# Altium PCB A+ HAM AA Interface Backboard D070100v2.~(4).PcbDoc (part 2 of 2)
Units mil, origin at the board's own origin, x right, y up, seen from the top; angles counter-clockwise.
Board outline 2600 x 10000 mil, 6 copper layers (Top Layer, InternalPlane1, MidLayer1, InternalPlane3, InternalPlane4, Bottom Layer), stack 92.2 mil thick; 10 components, 66 nets, 166 pads, 1741 vias.
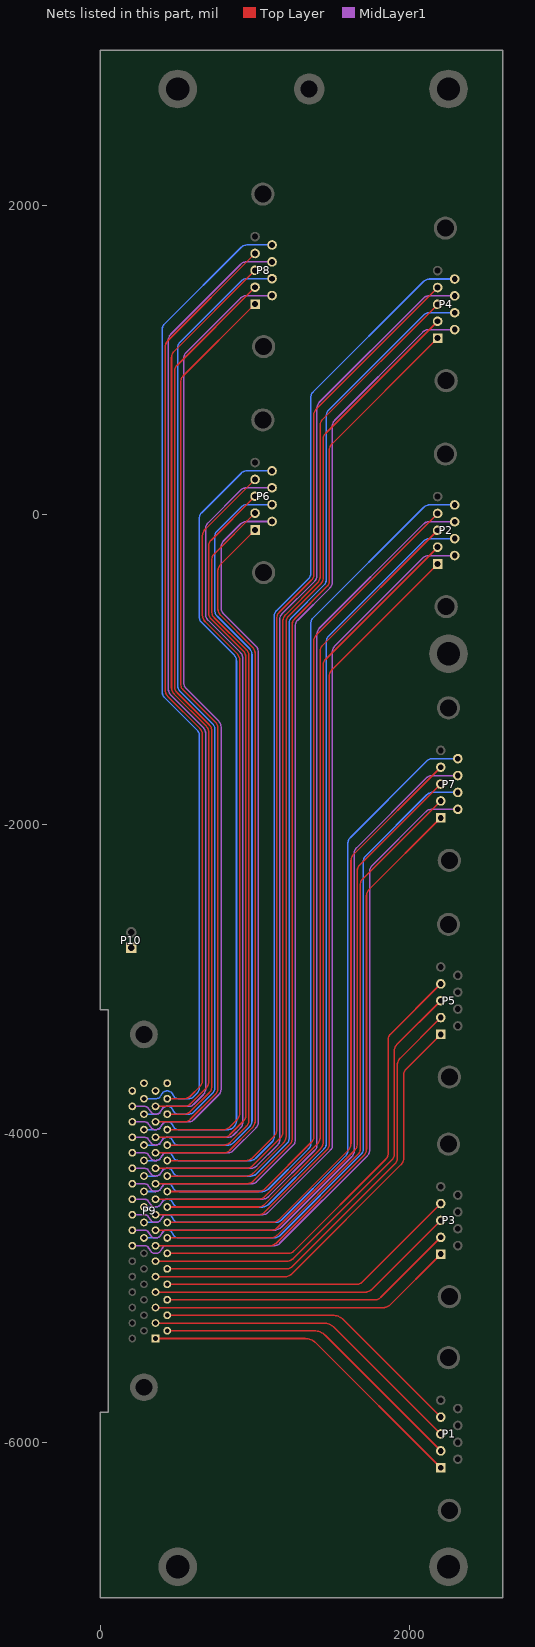
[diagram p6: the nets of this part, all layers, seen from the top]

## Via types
v1: diameter 12, hole 10, Top Layer to Bottom Layer, 1741 vias

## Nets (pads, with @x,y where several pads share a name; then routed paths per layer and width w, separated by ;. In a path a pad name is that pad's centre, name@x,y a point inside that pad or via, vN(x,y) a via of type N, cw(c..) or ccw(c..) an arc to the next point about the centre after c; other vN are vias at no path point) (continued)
OUTPUTN13: P7.6 P9.47 | length 4398.4
  MidLayer1 w10: P9.47@206.81,-4725 280,-4725 ; 281.81,-4725 cw(c281.81,-4775) 307.3,-4731.99 ; 406.18,-4732.07 382.54,-4767.87 cw(c356.81,-4725) 356.81,-4775 cw(c356.81,-4725) 331.08,-4767.87 307.44,-4732.07 ; 406.32,-4731.99 cw(c431.81,-4775) 431.81,-4725 1123.79,-4725 ccw(c1123.79,-4673.79) 1159.98,-4710.02 1725.03,-4144.97 ccw(c1688.79,-4108.79) 1740,-4108.81 ; 1740,-4105 1740,-4108.79 ; 1740,-2315 1740,-2306.21 ; 1740,-2306.15 cw(c1791.21,-2306.21) 1740,-2306.07 ; 2141.19,-1905 ccw(c2141.21,-1956.21) 2141.07,-1905 ; P7.6@2310,-1905 2141.07,-1905 ; 307.3,-4731.99 cw(c356.81,-4725) 307.28,-4731.82 307.44,-4732.07 ; 307.3,-4731.99 cw(c281.81,-4775) 307.44,-4732.07 ; 1740,-4108.81 1740,-2306.07 ; 1740,-2306.07 cw(c1791.21,-2306.21) 1754.94,-2270.06 cw(c1791.21,-2306.21) 1755,-2270 2105.06,-1919.94 cw(c2141.21,-1956.21) 2141.07,-1905
OUTPUTN14: P7.7 P9.48 | length 4366.6
  Bottom Layer w10: P9.48@281.81,-4675 355,-4675 ; 356.81,-4675 ccw(c356.81,-4625) 382.3,-4668.01 ; 481.18,-4667.93 457.54,-4632.13 ccw(c431.81,-4675) 431.81,-4625 ccw(c431.81,-4675) 406.08,-4632.13 382.44,-4667.93 ; 481.32,-4668.01 ccw(c506.81,-4625) 506.81,-4675 1124,-4675 ccw(c1124,-4624.3) 1159.83,-4660.17 1685.17,-4134.83 ccw(c1649.3,-4099) 1700,-4099 1700,-2242 cw(c1750.7,-2242) 1714.83,-2206.17 2110.17,-1810.83 cw(c2146,-1846.7) 2146,-1796 P7.7@2310,-1796 ; 382.3,-4668.01 ccw(c356.81,-4625) 382.44,-4667.93 ; 382.3,-4668.01 ccw(c431.81,-4675) 382.28,-4668.18 382.44,-4667.93
OUTPUTN15: P7.8 P9.49 | length 4508.1
  MidLayer1 w10: P9.49@206.81,-4625 280,-4625 ; 281.81,-4625 cw(c281.81,-4675) 307.3,-4631.99 ; 406.18,-4632.07 382.54,-4667.87 cw(c356.81,-4625) 356.81,-4675 cw(c356.81,-4625) 331.08,-4667.87 307.44,-4632.07 ; 406.32,-4631.99 cw(c431.81,-4675) 431.81,-4625 1123.79,-4625 ccw(c1123.79,-4561.72) 1168.46,-4606.54 ; 1170,-4605 1168.54,-4606.46 cw(c1123.79,-4561.72) 1168.46,-4606.54 ; 1640,-2195 1640,-2191.21 ; 2106.53,-1703.47 1655,-2155 ccw(c1691.21,-2191.21) 1640,-2191.2 ; 2108.06,-1701.94 cw(c2144.21,-1738.21) 2144.07,-1687 ; 2144.19,-1687 ccw(c2144.21,-1738.21) 2144.07,-1687 ; P7.8@2310,-1687 2144.07,-1687 ; 307.3,-4631.99 cw(c281.81,-4675) 307.44,-4632.07 ; 307.3,-4631.99 cw(c356.81,-4625) 307.28,-4631.82 307.44,-4632.07 ; 1168.46,-4606.54 1625,-4150 1625.86,-4149.14 ccw(c1591.72,-4115) 1640,-4115.01 1640,-2191.21
OUTPUTN16: P7.9 P9.50 | length 4490.4
  Bottom Layer w10: P9.50@281.81,-4575 355,-4575 ; 356.81,-4575 ccw(c356.81,-4525) 382.3,-4568.01 ; 481.18,-4567.93 457.54,-4532.13 ccw(c431.81,-4575) 431.81,-4525 ccw(c431.81,-4575) 406.08,-4532.13 382.44,-4567.93 ; 481.32,-4568.01 ccw(c506.81,-4525) 506.81,-4575 1134,-4575 ccw(c1134,-4524.3) 1169.83,-4560.17 1585.17,-4144.83 ccw(c1549.3,-4109) 1600,-4109 1600,-2124 cw(c1650.7,-2124) 1614.83,-2088.17 2110.17,-1592.83 cw(c2146,-1628.7) 2146,-1578 P7.9@2310,-1578 ; 382.3,-4568.01 ccw(c356.81,-4525) 382.44,-4567.93 ; 382.3,-4568.01 ccw(c431.81,-4575) 382.28,-4568.18 382.44,-4567.93
OUTPUTN17: P2.6 P9.51 | length 5772.2
  MidLayer1 w10: P9.51@206.81,-4525 280,-4525 ; 281.81,-4525 cw(c281.81,-4575) 307.3,-4531.99 ; 406.18,-4532.07 382.54,-4567.87 cw(c356.81,-4525) 356.81,-4575 cw(c356.81,-4525) 331.08,-4567.87 307.44,-4532.07 ; 406.32,-4531.99 cw(c431.81,-4575) 431.81,-4525 1045,-4525 ccw(c1045,-4467.06) 1085.97,-4508.03 1486.57,-4107.43 ; 1486.59,-4107.41 ccw(c1454.13,-4075) 1500,-4075 1500,-895 1500,-886.21 cw(c1551.21,-886.21) 1514.99,-850.01 2080,-285 2082.32,-282.68 cw(c2125,-325.36) 2125,-265 P2.6@2290,-265 ; 307.3,-4531.99 cw(c281.81,-4575) 307.44,-4532.07 ; 307.3,-4531.99 cw(c356.81,-4525) 307.28,-4531.82 307.44,-4532.07
OUTPUTN18: P2.7 P9.52 | length 5754.3
  Bottom Layer w10: P9.52@281.81,-4475 355,-4475 ; 356.81,-4475 ccw(c356.81,-4425) 382.3,-4468.01 ; 481.18,-4467.93 457.54,-4432.13 ccw(c431.81,-4475) 431.81,-4425 ccw(c431.81,-4475) 406.08,-4432.13 382.44,-4467.93 ; 481.32,-4468.01 ccw(c506.81,-4425) 506.81,-4475 ; 506.64,-4475 1048.83,-4475 ; 1049,-4475 ccw(c1049,-4424.3) 1084.83,-4460.17 1445.17,-4099.83 ccw(c1409.3,-4064) 1460,-4064 1460,-822 cw(c1510.7,-822) 1474.83,-786.17 2090.17,-170.83 cw(c2126,-206.7) 2126,-156 P2.7@2290,-156 ; 382.3,-4468.01 ccw(c356.81,-4425) 382.44,-4467.93 ; 382.3,-4468.01 ccw(c431.81,-4475) 382.28,-4468.18 382.44,-4467.93
OUTPUTN19: P2.8 P9.53 | length 5898.5
  MidLayer1 w10: P9.53@206.81,-4425 280,-4425 ; 281.81,-4425 cw(c281.81,-4475) 307.3,-4431.99 ; 406.18,-4432.07 382.54,-4467.87 cw(c356.81,-4425) 356.81,-4475 cw(c356.81,-4425) 331.08,-4467.87 307.44,-4432.07 ; 406.32,-4431.99 cw(c431.81,-4475) 431.81,-4425 1045.25,-4425 ccw(c1045.25,-4365.25) 1087.5,-4407.5 1385.86,-4109.14 ccw(c1351.72,-4075) 1400,-4075.02 1400,-771.21 ; 1400,-780 1400,-771.21 ; P2.8@2290,-47 2120,-47 ccw(c2120,-88.04) 2090.98,-59.02 2085,-65 1415,-735 ccw(c1451.21,-771.21) 1400,-771.19 ; 307.3,-4431.99 cw(c281.81,-4475) 307.44,-4432.07 ; 307.3,-4431.99 cw(c356.81,-4425) 307.28,-4431.82 307.44,-4432.07
OUTPUTN20: P2.9 P9.54 | length 5872.3
  Bottom Layer w10: P9.54@281.81,-4375 355,-4375 ; 356.81,-4375 ccw(c356.81,-4325) 382.3,-4368.01 ; 481.18,-4367.93 457.54,-4332.13 ccw(c431.81,-4375) 431.81,-4325 ccw(c431.81,-4375) 406.08,-4332.13 382.44,-4367.93 ; 481.32,-4368.01 ccw(c506.81,-4325) 506.81,-4375 1049,-4375 ccw(c1049,-4324.3) 1084.83,-4360.17 1345.17,-4099.83 ccw(c1309.3,-4064) 1360,-4064 1360,-704 cw(c1410.7,-704) 1374.83,-668.17 2090.17,47.17 cw(c2126,11.3) 2126,62 P2.9@2290,62 ; 382.3,-4368.01 ccw(c356.81,-4325) 382.44,-4367.93 ; 382.3,-4368.01 ccw(c431.81,-4375) 382.28,-4368.18 382.44,-4367.93
OUTPUTN21: P4.6 P9.55 | length 6988.5
  MidLayer1 w10: P9.55@206.81,-4325 280,-4325 ; 281.81,-4325 cw(c281.81,-4375) 307.3,-4331.99 ; 406.18,-4332.07 382.54,-4367.87 cw(c356.81,-4325) 356.81,-4375 cw(c356.81,-4325) 331.08,-4367.87 307.44,-4332.07 ; 406.32,-4331.99 cw(c431.81,-4375) 431.81,-4325 975,-4325 ccw(c975,-4271.89) 1012.54,-4309.46 1247,-4075 ccw(c1215.62,-4043.62) 1260,-4043.62 ; 1260,-4045 1260,-720 1260,-719.21 cw(c1311.21,-719.21) 1275,-683 1483.75,-474.25 ; 1483,-475 1483.74,-474.26 ; P4.6@2290,1195 2121.21,1195 ccw(c2121.21,1143.79) 2085,1180 1515,610 ccw(c1551.21,573.79) 1500,573.79 1500,-435 cw(c1444.48,-435) 1483.75,-474.25 ; 307.3,-4331.99 cw(c281.81,-4375) 307.44,-4332.07 ; 307.3,-4331.99 cw(c356.81,-4325) 307.28,-4331.82 307.44,-4332.07
OUTPUTN22: P4.7 P9.56 | length 6966.2
  Bottom Layer w10: P9.56@281.81,-4275 355,-4275 ; 356.81,-4275 ccw(c356.81,-4225) 382.3,-4268.01 ; 481.18,-4267.93 457.54,-4232.13 ccw(c431.81,-4275) 431.81,-4225 ccw(c431.81,-4275) 406.08,-4232.13 382.44,-4267.93 ; 481.32,-4268.01 ccw(c506.81,-4225) 506.81,-4275 974,-4275 ccw(c974,-4224.3) 1009.83,-4260.17 1205.17,-4064.83 ccw(c1169.3,-4029) 1220,-4029 1220,-702.43 cw(c1270.7,-702.43) 1234.76,-666.67 ; 1234.83,-666.6 ccw(c1270.7,-702.43) 1234.76,-666.67 ; 1474.82,673.82 ccw(c1510.7,638) 1460,638 1460,-420.43 cw(c1409.3,-420.43) 1445.17,-456.26 1234.76,-666.67 ; 1474.83,673.83 2090.17,1289.17 cw(c2126,1253.3) 2126,1304 P4.7@2290,1304 ; 382.3,-4268.01 ccw(c356.81,-4225) 382.44,-4267.93 ; 382.3,-4268.01 ccw(c431.81,-4275) 382.28,-4268.18 382.44,-4267.93
OUTPUTN23: P4.8 P9.57 | length 7103.5
  MidLayer1 w10: P9.57@206.81,-4225 280,-4225 ; 281.81,-4225 cw(c281.81,-4275) 307.3,-4231.99 ; 406.18,-4232.07 382.54,-4267.87 cw(c356.81,-4225) 356.81,-4275 cw(c356.81,-4225) 331.08,-4267.87 307.44,-4232.07 ; 406.32,-4231.99 cw(c431.81,-4275) 431.81,-4225 975,-4225 ccw(c975,-4176.72) 1009.12,-4210.88 ; 1009.14,-4210.86 1145.86,-4074.14 ccw(c1111.72,-4040) 1160,-4040 1160,-675 1160,-672.95 cw(c1199.53,-672.95) 1171.56,-645.02 1381.23,-435.35 ccw(c1335.84,-390) 1400,-390.44 ; 1380,-436.58 1381.21,-435.37 ; 1400,-390 cw(c1335.84,-390) 1400,-390.44 ; P4.8@2290,1413 2124.21,1413 ccw(c2124.21,1361.79) 2088,1398 1415,725 ccw(c1451.21,688.79) 1400,688.79 1400,-380 1400,-390.44 ; 307.3,-4231.99 cw(c356.81,-4225) 307.28,-4231.82 307.44,-4232.07 ; 307.3,-4231.99 cw(c281.81,-4275) 307.44,-4232.07
OUTPUTN24: P4.9 P9.58 | length 7081.4
  Bottom Layer w10: P9.58@281.81,-4175 355,-4175 ; 356.81,-4175 ccw(c356.81,-4125) 382.3,-4168.01 ; 481.18,-4167.93 457.54,-4132.13 ccw(c431.81,-4175) 431.81,-4125 ccw(c431.81,-4175) 406.08,-4132.13 382.44,-4167.93 ; 481.32,-4168.01 ccw(c506.81,-4125) 506.81,-4175 969,-4175 ccw(c969,-4124.3) 1004.83,-4160.17 1108.09,-4056.91 ccw(c1072.22,-4021.08) 1122.92,-4021.08 1122.92,-658.09 cw(c1173.62,-658.09) 1137.66,-622.35 ; 1137.74,-622.27 ccw(c1173.62,-658.09) 1137.66,-622.35 ; 1374.83,791.83 ccw(c1410.7,756) 1374.69,791.69 ; P4.9@2290,1522 2126,1522 ccw(c2126,1471.3) 2090.17,1507.17 1374.69,791.69 ; 382.3,-4168.01 ccw(c356.81,-4125) 382.44,-4167.93 ; 382.3,-4168.01 ccw(c431.81,-4175) 382.28,-4168.18 382.44,-4167.93 ; 1137.66,-622.35 1345.17,-414.84 ccw(c1309.3,-379.01) 1360,-379.01 1360,756 cw(c1410.7,756) 1374.69,791.69
OUTPUTN25: P6.6 P9.59 | length 5165.2
  MidLayer1 w10: P9.59@206.81,-4125 280,-4125 ; 281.81,-4125 cw(c281.81,-4175) 307.3,-4131.99 ; 406.18,-4132.07 382.54,-4167.87 cw(c356.81,-4125) 356.81,-4175 cw(c356.81,-4125) 331.08,-4167.87 307.44,-4132.07 ; 406.32,-4131.99 cw(c431.81,-4175) 431.81,-4125 820,-4125 ccw(c820,-4064.64) 862.68,-4107.32 1005.86,-3964.14 ; 1005.88,-3964.12 ccw(c971.72,-3930) 1020,-3930 1020,-2792 1020,-1500 1020,-886.45 ; 1020,-886.66 ccw(c968.79,-886.66) 1020,-886.45 ; P6.6@1110,-45 944.21,-45 ccw(c944.21,-96.21) 908,-60 795,-173 ccw(c831.21,-209.21) 780,-209.21 780,-604.23 ccw(c831.21,-604.23) 795,-640.44 1005,-850.44 cw(c968.79,-886.66) 1020,-886.45 ; 307.3,-4131.99 cw(c281.81,-4175) 307.44,-4132.07 ; 307.3,-4131.99 cw(c356.81,-4125) 307.28,-4131.82 307.44,-4132.07
OUTPUTN26: P6.7 P9.60 | length 5148.4
  Bottom Layer w10: P9.60@281.81,-4075 355,-4075 ; 356.81,-4075 ccw(c356.81,-4025) 382.3,-4068.01 ; 481.18,-4067.93 457.54,-4032.13 ccw(c431.81,-4075) 431.81,-4025 ccw(c431.81,-4075) 406.08,-4032.13 382.44,-4067.93 ; 481.32,-4068.01 ccw(c506.81,-4025) 506.81,-4075 824,-4075 ccw(c824,-4024.3) 859.83,-4060.17 965.17,-3954.83 ccw(c929.3,-3919) 980,-3919 980,-2785 980,-1500 980,-902.81 ; 980,-903.01 ccw(c929.3,-903.01) 980,-902.81 ; P6.7@1110,64 946,64 ccw(c946,13.3) 910.17,49.17 754.83,-106.17 ccw(c790.7,-142) 740,-142 740,-621.01 ccw(c790.7,-621.01) 754.83,-656.84 965.17,-867.18 cw(c929.3,-903.01) 980,-902.81 ; 382.3,-4068.01 ccw(c356.81,-4025) 382.44,-4067.93 ; 382.3,-4068.01 ccw(c431.81,-4075) 382.28,-4068.18 382.44,-4067.93
OUTPUTN27: P6.8 P9.61 | length 5283.7
  MidLayer1 w10: P9.61@206.81,-4025 280,-4025 ; 281.81,-4025 cw(c281.81,-4075) 307.3,-4031.99 ; 406.18,-4032.07 382.54,-4067.87 cw(c356.81,-4025) 356.81,-4075 cw(c356.81,-4025) 331.08,-4067.87 307.44,-4032.07 ; 406.32,-4031.99 cw(c431.81,-4075) 431.81,-4025 825,-4025 ccw(c825,-3976.72) 859.12,-4010.88 ; 859.14,-4010.86 905.01,-3964.99 ccw(c868.79,-3928.79) 920,-3928.79 920,-2777.5 920,-1500 920,-927.85 ; 920,-928.08 ccw(c868.79,-928.08) 920,-927.85 ; P6.8@1110,173 944.21,173 ccw(c944.21,121.79) 908,158 695,-55 ccw(c731.21,-91.21) 680,-91.21 680,-645.65 ccw(c731.21,-645.65) 695,-681.86 905,-891.86 cw(c868.79,-928.08) 920,-927.85 ; 307.3,-4031.99 cw(c281.81,-4075) 307.44,-4032.07 ; 307.3,-4031.99 cw(c356.81,-4025) 307.28,-4031.82 307.44,-4032.07
OUTPUTN28: P6.9 P9.62 | length 5266.2
  Bottom Layer w10: P9.62@281.81,-3975 355,-3975 ; 356.81,-3975 ccw(c356.81,-3925) 382.3,-3968.01 ; 481.18,-3967.93 457.54,-3932.13 ccw(c431.81,-3975) 431.81,-3925 ccw(c431.81,-3975) 406.08,-3932.13 382.44,-3967.93 ; 481.32,-3968.01 ccw(c506.81,-3925) 506.81,-3975 824,-3975 ccw(c824,-3924.3) 859.83,-3960.17 865.17,-3954.83 ccw(c829.3,-3919) 880,-3919 880,-2715.75 880,-1500 880,-944.43 ccw(c829.3,-944.43) 865.17,-908.6 654.83,-698.26 cw(c690.7,-662.43) 640,-662.43 640,-24 cw(c690.7,-24) 654.83,11.83 910.17,267.17 cw(c946,231.3) 946,282 P6.9@1110,282 ; 382.3,-3968.01 ccw(c356.81,-3925) 382.44,-3967.93 ; 382.3,-3968.01 ccw(c431.81,-3975) 382.28,-3968.18 382.44,-3967.93
OUTPUTN29: P8.6 P9.63 | length 6280
  MidLayer1 w10: P9.63@206.81,-3925 280,-3925 ; 281.81,-3925 cw(c281.81,-3975) 307.3,-3931.99 ; 406.18,-3932.07 382.54,-3967.87 cw(c356.81,-3925) 356.81,-3975 cw(c356.81,-3925) 331.08,-3967.87 307.44,-3932.07 ; 406.32,-3931.99 cw(c431.81,-3975) 431.81,-3925 570,-3925 ccw(c570,-3876.72) 604.12,-3910.88 ; 604.14,-3910.86 765.86,-3749.14 ccw(c731.72,-3715) 780,-3715.01 780,-1371.21 ; 780,-1375 780,-1371.21 ; P8.6@1110,1415 944.21,1415 ccw(c944.21,1363.79) 908,1400 555,1047 ccw(c591.21,1010.79) 540,1010.81 540,-1088.79 ccw(c591.21,-1088.79) 555,-1125 765,-1335 cw(c728.79,-1371.21) 780,-1371.21 ; 307.3,-3931.99 cw(c356.81,-3925) 307.28,-3931.82 307.44,-3932.07 ; 307.3,-3931.99 cw(c281.81,-3975) 307.44,-3932.07
OUTPUTN30: P8.7 P9.64 | length 6259
  Bottom Layer w10: P9.64@281.81,-3875 355,-3875 ; 356.81,-3875 ccw(c356.81,-3825) 382.3,-3868.01 ; 481.18,-3867.93 457.54,-3832.13 ccw(c431.81,-3875) 431.81,-3825 ccw(c431.81,-3875) 406.08,-3832.13 382.44,-3867.93 ; 481.32,-3868.01 ccw(c506.81,-3825) 506.81,-3875 569,-3875 ccw(c569,-3824.3) 604.83,-3860.17 725.17,-3739.83 ccw(c689.3,-3704) 740,-3704.1 ; 740,-3704 cw(c689.3,-3704) 740,-3704.1 ; P8.7@1110,1524 946,1524 ccw(c946,1473.3) 910.17,1509.17 514.83,1113.83 ccw(c550.7,1078) 500,1078 500,-1105.57 ccw(c550.7,-1105.57) 514.83,-1141.4 725.17,-1351.74 cw(c689.3,-1387.57) 740,-1387.57 740,-3704.1 ; 382.3,-3868.01 ccw(c356.81,-3825) 382.44,-3867.93 ; 382.3,-3868.01 ccw(c431.81,-3875) 382.28,-3868.18 382.44,-3867.93
OUTPUTN31: P8.8 P9.65 | length 6394.1
  MidLayer1 w10: P9.65@206.81,-3825 280,-3825 ; 281.81,-3825 cw(c281.81,-3875) 307.3,-3831.99 ; 406.18,-3832.07 382.54,-3867.87 cw(c356.81,-3825) 356.81,-3875 cw(c356.81,-3825) 331.08,-3867.87 307.44,-3832.07 ; 406.32,-3831.99 cw(c431.81,-3875) 431.81,-3825 570,-3825 ccw(c570,-3776.72) 604.12,-3810.88 ; 604.14,-3810.86 665.03,-3749.97 ccw(c628.79,-3713.79) 680,-3713.8 680,-1412.63 ccw(c628.79,-1412.63) 665,-1376.42 455,-1166.42 cw(c491.21,-1130.21) 440,-1130.21 440,-1125 440,1050 440,1128.79 cw(c491.21,1128.79) 455,1165 908,1618 cw(c944.21,1581.79) 944.21,1633 P8.8@1110,1633 ; 307.3,-3831.99 cw(c356.81,-3825) 307.28,-3831.82 307.44,-3832.07 ; 307.3,-3831.99 cw(c281.81,-3875) 307.44,-3832.07
OUTPUTN32: P8.9 P9.66 | length 6377
  Bottom Layer w10: P9.66@281.81,-3775 355,-3775 ; 356.81,-3775 ccw(c356.81,-3725) 382.3,-3768.01 ; 481.18,-3767.93 457.54,-3732.13 ccw(c431.81,-3775) 431.81,-3725 ccw(c431.81,-3775) 406.08,-3732.13 382.44,-3767.93 ; 481.32,-3768.01 ccw(c506.81,-3725) 506.81,-3775 569,-3775 ccw(c569,-3724.3) 604.83,-3760.17 625.17,-3739.83 ccw(c589.3,-3704) 640,-3704.1 ; 640,-3704 cw(c589.3,-3704) 640,-3704.1 ; P8.9@1110,1742 946,1742 ccw(c946,1691.3) 910.17,1727.17 414.83,1231.83 ccw(c450.7,1196) 400,1196 400,-1146.99 ccw(c450.7,-1146.99) 414.83,-1182.82 625.17,-1393.16 cw(c589.3,-1428.99) 640,-1428.99 640,-3704.1 ; 382.3,-3768.01 ccw(c356.81,-3725) 382.44,-3767.93 ; 382.3,-3768.01 ccw(c431.81,-3775) 382.28,-3768.18 382.44,-3767.93
OUTPUTP1: P1.1 P9.1 | length 2184.8
  Top Layer w10: P9.1@356.81,-5325 1323.58,-5325 cw(c1323.58,-5425) 1394.29,-5354.29 P1.1@2200,-6160
OUTPUTP2: P1.2 P9.2 | length 2085.3
  Top Layer w10: P9.2@431.81,-5275 1382.58,-5275 cw(c1382.58,-5375) 1453.29,-5304.29 P1.2@2200,-6051
OUTPUTP3: P1.3 P9.3 | length 2135.9
  Top Layer w10: P9.3@356.81,-5225 1441.58,-5225 cw(c1441.58,-5325) 1512.29,-5254.29 P1.3@2200,-5942
OUTPUTP4: P1.4 P9.4 | length 2036.4
  Top Layer w10: P9.4@431.81,-5175 1500.58,-5175 cw(c1500.58,-5275) 1571.29,-5204.29 P1.4@2200,-5833
OUTPUTP5: P3.1 P9.5 | length 1983.9
  Top Layer w10: P9.5@356.81,-5125 1832.11,-5125 ; 1832,-5125 ccw(c1832,-5069.47) 1832.11,-5125 ; P3.1@2200,-4780 1871.26,-5108.74 ; 1832.11,-5125 ccw(c1832,-5069.47) 1871.2,-5108.8 ; 1871.2,-5108.8 ccw(c1832,-5069.47) 1871.26,-5108.74 ; 1871.2,-5108.8 1871.26,-5108.74
OUTPUTP6: P3.2 P9.6 | length 1933.2
  Top Layer w10: P9.6@431.81,-5075 1773,-5075 ccw(c1773,-5019.47) 1812.2,-5058.8 ; P3.2@2200,-4671 1812.26,-5058.74 ; 1812.2,-5058.8 ccw(c1773,-5019.47) 1812.26,-5058.74 ; 1812.2,-5058.8 1812.26,-5058.74
OUTPUTP7: P3.3 P9.7 | length 2032.7
  Top Layer w10: P9.7@356.81,-5025 1714,-5025 ccw(c1714,-4969.47) 1753.2,-5008.8 ; P3.3@2200,-4562 1753.26,-5008.74 ; 1753.2,-5008.8 ccw(c1714,-4969.47) 1753.26,-5008.74 ; 1753.2,-5008.8 1753.26,-5008.74
OUTPUTP8: P3.4 P9.8 | length 1982.1
  Top Layer w10: P9.8@431.81,-4975 1655,-4975 ccw(c1655,-4919.47) 1694.2,-4958.8 ; P3.4@2200,-4453 1694.26,-4958.74 ; 1694.2,-4958.8 ccw(c1655,-4919.47) 1694.26,-4958.74 ; 1694.2,-4958.8 1694.26,-4958.74
OUTPUTP9: P5.1 P9.9 | length 2827
  Top Layer w10: P9.9@356.81,-4925 1197,-4925 ccw(c1197,-4869.47) 1236.26,-4908.74 1943.74,-4201.26 ; P5.1@2200,-3360 1976.26,-3583.74 ccw(c2015.53,-3623) 1960,-3623 1960,-4162 cw(c1904.47,-4162) 1943.8,-4201.2 ; 1943.74,-4201.26 ccw(c1904.47,-4162) 1943.8,-4201.2 ; 1943.74,-4201.26 1943.8,-4201.2
OUTPUTP10: P5.2 P9.10 | length 2817
  Top Layer w10: P9.10@431.81,-4875 1202,-4875 ccw(c1202,-4819.47) 1241.26,-4858.74 1903.74,-4196.26 ; 1920,-4160 1920,-3554 cw(c1975.53,-3554) 1936.26,-3514.74 P5.2@2200,-3251 ; 1920,-4157 cw(c1864.47,-4157) 1903.8,-4196.2 ; 1903.74,-4196.26 ccw(c1864.47,-4157) 1903.8,-4196.2 ; 1903.74,-4196.26 1903.8,-4196.2
OUTPUTP11: P5.3 P9.11 | length 2950.5
  Top Layer w10: P9.11@356.81,-4825 1207,-4825 ccw(c1207,-4769.47) 1246.26,-4808.74 1883.74,-4171.26 ; 1900,-4132 cw(c1844.47,-4132) 1899.61,-4138.58 cw(c1844.47,-4132) 1883.8,-4171.2 ; 1900,-4131.61 1900,-3465 cw(c1955.53,-3465) 1916.26,-3425.74 P5.3@2200,-3142 ; 1883.74,-4171.26 ccw(c1844.47,-4132) 1883.8,-4171.2 ; 1883.74,-4171.26 1883.8,-4171.2
OUTPUTP12: P5.4 P9.12 | length 2938.4
  Top Layer w10: P9.12@431.81,-4775 1213,-4775 ccw(c1213,-4719.47) 1252.26,-4758.74 1843.74,-4167.26 ; P5.4@2200,-3033 1876.26,-3356.74 ccw(c1915.53,-3396) 1860,-3396 1860,-4128 cw(c1804.47,-4128) 1843.8,-4167.2 ; 1843.74,-4167.26 ccw(c1804.47,-4128) 1843.8,-4167.2 ; 1843.74,-4167.26 1843.8,-4167.2
OUTPUTP13: P7.1 P9.13 | length 3968.5
  Top Layer w10: P9.13@356.81,-4725 1097,-4725 ccw(c1097,-4669.47) 1136.26,-4708.74 1703.74,-4141.26 ; P7.1@2200,-1960 1736.26,-2423.74 ccw(c1775.53,-2463) 1720,-2463 1720,-4102 cw(c1664.47,-4102) 1703.8,-4141.2 ; 1703.74,-4141.26 ccw(c1664.47,-4102) 1703.8,-4141.2 ; 1703.74,-4141.26 1703.8,-4141.2
OUTPUTP14: P7.2 P9.14 | length 3954.6
  Top Layer w10: P9.14@431.81,-4675 1102,-4675 ccw(c1102,-4619.47) 1141.26,-4658.74 1663.74,-4136.26 ccw(c1624.47,-4097) 1680,-4097.01 ; 1680,-4095 1680,-2392.82 ; 1680,-2393.99 1680,-2392.92 cw(c1732.92,-2392.92) 1680,-2392.82 ; P7.2@2200,-1851 1695.5,-2355.5 ccw(c1732.92,-2392.92) 1680,-2392.82
OUTPUTP15: P7.3 P9.15 | length 4090.5
  Top Layer w10: P9.15@356.81,-4625 1104,-4625 ccw(c1104,-4569.47) 1143.26,-4608.74 1643.74,-4108.26 ccw(c1604.47,-4069) 1660,-4069 1660,-2305 cw(c1715.53,-2305) 1676.26,-2265.74 P7.3@2200,-1742
OUTPUTP16: P7.4 P9.16 | length 4079.2
  Top Layer w10: P9.16@431.81,-4575 1112,-4575 ccw(c1112,-4519.47) 1151.26,-4558.74 1603.74,-4106.26 ; P7.4@2200,-1633 1636.26,-2196.74 ccw(c1675.53,-2236) 1620,-2236 1620,-4067 cw(c1564.47,-4067) 1603.8,-4106.2 ; 1603.74,-4106.26 ccw(c1564.47,-4067) 1603.8,-4106.2 ; 1603.74,-4106.26 1603.8,-4106.2
OUTPUTP17: P2.1 P9.17 | length 5356.2
  Top Layer w10: P9.17@356.81,-4525 1022,-4525 ccw(c1022,-4469.47) 1061.26,-4508.74 1463.74,-4106.26 ; P2.1@2180,-320 1496.26,-1003.74 ccw(c1535.53,-1043) 1480,-1043 1480,-4067 cw(c1424.47,-4067) 1463.8,-4106.2 ; 1463.74,-4106.26 ccw(c1424.47,-4067) 1463.8,-4106.2 ; 1463.74,-4106.26 1463.8,-4106.2
OUTPUTP18: P2.2 P9.18 | length 5343.3
  Top Layer w10: P9.18@431.81,-4475 1022.15,-4475 ; 1022,-4475 ccw(c1022,-4419.47) 1022.15,-4475 ; 1024.89,-4475 ccw(c1024.89,-4419.47) 1025.04,-4475 1022.15,-4475 ; P2.2@2180,-211 1456.26,-934.74 ccw(c1495.53,-974) 1440,-974 1440,-4057 cw(c1384.47,-4057) 1423.74,-4096.26 1061.26,-4458.74 cw(c1022,-4419.47) 1022.15,-4475
OUTPUTP19: P2.3 P9.19 | length 5474.2
  Top Layer w10: P9.19@356.81,-4425 1022,-4425 ccw(c1022,-4369.47) 1061.26,-4408.74 1403.74,-4066.26 ccw(c1364.47,-4027) 1420,-4027 1420,-885 cw(c1475.53,-885) 1436.26,-845.74 P2.3@2180,-102
OUTPUTP20: P2.4 P9.20 | length 5458.7
  Top Layer w10: P9.20@431.81,-4375 1023,-4375 ccw(c1023,-4319.47) 1062.2,-4358.8 1363.74,-4057.26 ccw(c1324.47,-4018) 1380,-4018 1380,-816 cw(c1435.53,-816) 1396.26,-776.74 P2.4@2180,7
OUTPUTP21: P4.1 P9.21 | length 6567.9
  Top Layer w10: P9.21@356.81,-4325 947,-4325 ccw(c947,-4269.47) 986.2,-4308.8 ; 986.26,-4308.74 1223.74,-4071.26 ; 1256.26,-673.45 ccw(c1295.53,-712.72) 1256.18,-673.54 ; 1480,417 cw(c1535.53,417) 1480,417.33 ; P4.1@2180,1140 1496.26,456.26 ccw(c1535.53,417) 1480,417.33 ; 1223.74,-4071.26 ccw(c1184.47,-4032) 1223.8,-4071.2 ; 1223.74,-4071.26 1223.8,-4071.2 ; 1223.8,-4071.2 ccw(c1184.47,-4032) 1240,-4032 1240,-712.72 cw(c1295.53,-712.72) 1256.18,-673.54 ; 1256.18,-673.54 1463.74,-465.98 ccw(c1424.47,-426.71) 1480,-426.71 1480,417.33
OUTPUTP22: P4.2 P9.22 | length 6551.6
  Top Layer w10: P9.22@431.81,-4275 947,-4275 ccw(c947,-4219.47) 986.2,-4258.8 986.26,-4258.74 1183.74,-4061.26 ; P4.2@2180,1249 1456.26,525.26 ccw(c1495.53,486) 1440,486 1440,-410.15 cw(c1384.47,-410.15) 1423.76,-449.38 1216.24,-656.91 ccw(c1255.53,-696.15) 1200,-696.15 1200,-4022 cw(c1144.47,-4022) 1183.8,-4061.2 ; 1183.74,-4061.26 ccw(c1144.47,-4022) 1183.8,-4061.2 ; 1183.74,-4061.26 1183.8,-4061.2
OUTPUTP23: P4.3 P9.23 | length 6683.8
  Top Layer w10: P9.23@356.81,-4225 944,-4225 ccw(c944,-4169.47) 983.2,-4208.8 983.26,-4208.74 1163.73,-4028.27 ccw(c1124.47,-3989) 1180,-3989 1180,-687.86 cw(c1235.53,-687.86) 1196.24,-648.62 1403.76,-441.1 ccw(c1364.47,-401.86) 1420,-401.86 1420,575 cw(c1475.53,575) 1436.26,614.26 P4.3@2180,1358
OUTPUTP24: P4.4 P9.24 | length 6666.8
  Top Layer w10: P9.24@431.81,-4175 942,-4175 ccw(c942,-4119.47) 981.2,-4158.8 981.26,-4158.74 1123.74,-4016.26 ; 1156.26,-632.03 ccw(c1195.53,-671.29) 1156.16,-632.14 ; P4.4@2180,1467 1396.27,683.27 ccw(c1435.53,644) 1384.99,667 ccw(c1435.53,644) 1380,644 1380,-385.29 cw(c1324.47,-385.29) 1363.74,-424.56 1156.16,-632.14 ; 1123.74,-4016.26 ccw(c1084.47,-3977) 1123.8,-4016.2 ; 1123.74,-4016.26 1123.8,-4016.2 ; 1123.8,-4016.2 ccw(c1084.47,-3977) 1140,-3977 1140,-671.29 cw(c1195.53,-671.29) 1156.16,-632.14
OUTPUTP25: P6.1 P9.25 | length 4750
  Top Layer w10: P9.25@356.81,-4125 797,-4125 ccw(c797,-4069.47) 836.2,-4108.8 ; 1000,-896.73 ccw(c944.47,-896.73) 1000,-896.52 ; P6.1@1000,-100 776.26,-323.74 ccw(c815.53,-363) 760,-363 760,-610.73 ccw(c815.53,-610.73) 776.26,-649.99 983.74,-857.46 cw(c944.47,-896.73) 1000,-896.52 ; 836.2,-4108.8 ccw(c797,-4069.47) 836.26,-4108.74 ; 836.2,-4108.8 836.26,-4108.74 ; 836.26,-4108.74 983.74,-3961.26 ; 983.74,-3961.26 ccw(c944.47,-3922) 983.8,-3961.2 ; 983.74,-3961.26 983.8,-3961.2 ; 983.8,-3961.2 ccw(c944.47,-3922) 1000,-3922 1000,-2805.11 1000,-1500 1000,-896.52
OUTPUTP26: P6.2 P9.26 | length 4733.2
  Top Layer w10: P9.26@431.81,-4075 798.81,-4075 ccw(c798.81,-4019.47) 838.01,-4058.8 ; 942.62,-872.92 736.26,-666.56 cw(c775.53,-627.29) 720,-627.29 720,-294 cw(c775.53,-294) 736.26,-254.74 P6.2@1000,9 ; 943.74,-874.03 cw(c904.47,-913.3) 960,-913.3 960,-3913.81 cw(c904.47,-3913.81) 943.74,-3953.07 838.07,-4058.74 ; 838.01,-4058.8 ccw(c798.81,-4019.47) 838.07,-4058.74 ; 838.01,-4058.8 838.07,-4058.74
OUTPUTP27: P6.3 P9.27 | length 4867.7
  Top Layer w10: P9.27@356.81,-4025 797,-4025 ccw(c797,-3969.47) 836.2,-4008.8 ; P6.3@1000,118 716.26,-165.74 ccw(c755.53,-205) 700,-205 700,-635.58 ccw(c755.53,-635.58) 716.26,-674.84 923.74,-882.32 cw(c884.47,-921.58) 940,-921.58 940,-3882 cw(c884.47,-3882) 923.74,-3921.26 836.26,-4008.74 ; 836.2,-4008.8 ccw(c797,-3969.47) 836.26,-4008.74 ; 836.2,-4008.8 836.26,-4008.74
OUTPUTP28: P6.4 P9.28 | length 4851.9
  Top Layer w10: P9.28@431.81,-3975 797,-3975 ccw(c797,-3919.47) 836.26,-3958.74 883.74,-3911.26 ccw(c844.47,-3872) 900,-3872 900,-938.04 ; 900,-938.15 ccw(c844.47,-938.15) 900,-938.04 ; P6.4@1000,227 676.26,-96.74 ccw(c715.53,-136) 660,-136 660,-652.15 ccw(c715.53,-652.15) 676.26,-691.41 883.74,-898.88 ; 883.74,-898.88 cw(c844.47,-938.15) 883.82,-898.97 ; 883.74,-898.88 883.82,-898.97 ; 883.82,-898.97 cw(c844.47,-938.15) 900,-938.04
OUTPUTP29: P8.1 P9.29 | length 5860.5
  Top Layer w10: P9.29@356.81,-3925 542,-3925 ccw(c542,-3869.47) 581.2,-3908.8 ; 760,-3707 cw(c704.47,-3707) 760,-3707.11 ; P8.1@1000,1360 536.26,896.26 ccw(c575.53,857) 520,857 520,-1095.28 ccw(c575.53,-1095.28) 536.26,-1134.55 743.74,-1342.02 cw(c704.47,-1381.28) 760,-1381.28 760,-3707.11 ; 581.2,-3908.8 ccw(c542,-3869.47) 581.26,-3908.74 ; 581.2,-3908.8 581.26,-3908.74 ; 581.26,-3908.74 743.74,-3746.26 ; 743.74,-3746.26 ccw(c704.47,-3707) 743.8,-3746.2 ; 743.74,-3746.26 743.8,-3746.2 ; 743.8,-3746.2 ccw(c704.47,-3707) 760,-3707.11
OUTPUTP30: P8.2 P9.30 | length 5844.3
  Top Layer w10: P9.30@431.81,-3875 542,-3875 ccw(c542,-3819.47) 581.26,-3858.74 703.74,-3736.26 ccw(c664.47,-3697) 720,-3697.01 720,-1397.85 ccw(c664.47,-1397.85) 703.74,-1358.59 496.26,-1151.12 cw(c535.53,-1111.85) 480,-1111.85 480,926 cw(c535.53,926) 496.26,965.26 P8.2@1000,1469
OUTPUTP31: P8.3 P9.31 | length 5976.7
  Top Layer w10: P9.31@356.81,-3825 542,-3825 ccw(c542,-3769.47) 581.26,-3808.74 683.74,-3706.26 ccw(c644.47,-3667) 700,-3667.01 700,-1406.14 ccw(c644.47,-1406.14) 683.74,-1366.87 476.26,-1159.4 cw(c515.53,-1120.14) 460,-1120.14 ; 460,-1118.56 460,1015 cw(c515.53,1015) 476.26,1054.26 P8.3@1000,1578
OUTPUTP32: P8.4 P9.32 | length 5962.5
  Top Layer w10: 420,1084 cw(c475.53,1084) 420,1084.1 ; P9.32@431.81,-3775 542,-3775 ccw(c542,-3719.47) 581.26,-3758.74 643.74,-3696.26 ccw(c604.47,-3657) 660,-3657.11 ; 660,-3657 cw(c604.47,-3657) 660,-3657.11 ; P8.4@1000,1687 436.26,1123.26 ccw(c475.53,1084) 420,1084.1 ; 420,1084.1 420,-1136.71 ccw(c475.53,-1136.71) 436.26,-1175.97 643.74,-1383.44 cw(c604.47,-1422.71) 660,-1422.71 660,-3657.11
RTN: P9.33 P9.34 P9.67 P9.68 P10.1
pads on no net: P1.5 P2.5 P3.5 P4.5 P5.5 P6.5 P7.5 P8.5

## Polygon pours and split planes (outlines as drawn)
GND on InternalPlane1 (split plane): 2579.9,-6979.9 20.1,-6979.9 20.1,-5820.1 50,-5820.1 53.92,-5819.71 57.69,-5818.57 61.17,-5816.71 64.21,-5814.21 66.71,-5811.17 68.57,-5807.69 69.71,-5803.92 70.1,-5800 70.1,-3200 69.71,-3196.08 68.57,-3192.31 66.71,-3188.83 64.21,-3185.79 61.17,-3183.29 57.69,-3181.43 53.92,-3180.29 50,-3179.9 20.1,-3179.9 20.1,2979.9 2579.9,2979.9
RTN on InternalPlane3 (split plane): 2579.9,-6979.9 20.1,-6979.9 20.1,-5820.1 50,-5820.1 53.92,-5819.71 57.69,-5818.57 61.17,-5816.71 64.21,-5814.21 66.71,-5811.17 68.57,-5807.69 69.71,-5803.92 70.1,-5800 70.1,-3200 69.71,-3196.08 68.57,-3192.31 66.71,-3188.83 64.21,-3185.79 61.17,-3183.29 57.69,-3181.43 53.92,-3180.29 50,-3179.9 20.1,-3179.9 20.1,2979.9 2579.9,2979.9
GND on InternalPlane4 (split plane): 2579.9,-6979.9 20.1,-6979.9 20.1,-5820.1 50,-5820.1 53.92,-5819.71 57.69,-5818.57 61.17,-5816.71 64.21,-5814.21 66.71,-5811.17 68.57,-5807.69 69.71,-5803.92 70.1,-5800 70.1,-3200 69.71,-3196.08 68.57,-3192.31 66.71,-3188.83 64.21,-3185.79 61.17,-3183.29 57.69,-3181.43 53.92,-3180.29 50,-3179.9 20.1,-3179.9 20.1,2979.9 2579.9,2979.9

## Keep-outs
Keep-Out Layer:
  the board outline again, w10

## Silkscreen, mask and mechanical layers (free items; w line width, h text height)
Top Overlay:
  rectangle: 425,-6437.5 1675,-6062.5
  text "Chassis GND Connection" at 1000,2900 h40
  text "ADC AA Interface Board" at 500,2500 h100
  text "D070100-v2" at 500,2350 h100
  text "CH 29-32" at 770,1190 h100 r90
  text "CH 21-24" at 1950,985 h100 r90
  text "CH 25-28" at 770,-265 h100 r90
  text "CH 17-20" at 1950,-480 h100 r90
  text "CH 13-16" at 1950,-2110 h100 r90
  text "ADC RTN to GND Connection" at 300,-2700 h40
  text "Jumper Nominally Installed" at 300,-2800 h40
  text "CH 9-12" at 1950,-3470 h100 r90
  text "To ADC" at 750,-4750 h100 r90
  text "CH 5-8" at 1950,-4845 h100 r90
  text "SN:" at 190,-6180 h100
  text "CH 1-4" at 1950,-6215 h100 r90
Mechanical 1:
  lines w10: 0,-7000 2600,-7000 2600,3000 0,3000 0,-3200 50,-3200 50,-4500 50,-5800 0,-5800 0,-6500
